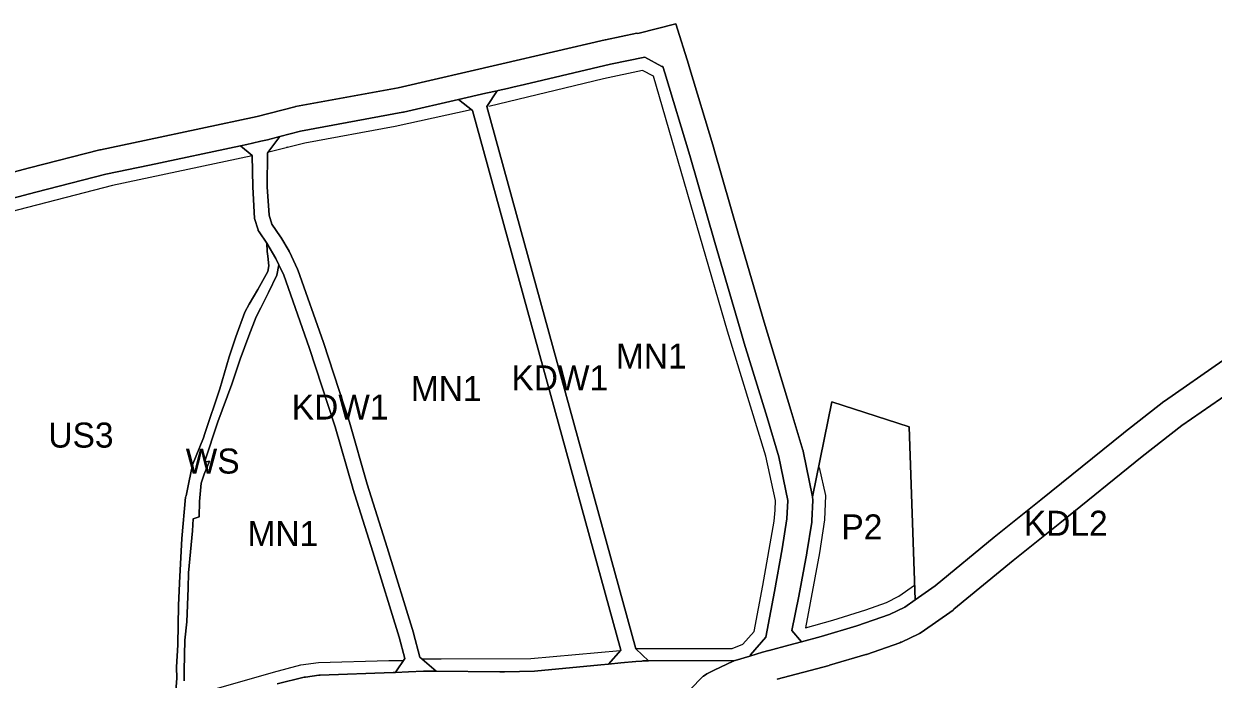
# Model space of a CAD drawing. Extents: x -284239 to -281592, y 34477 to 37267.
# Drawn here: x -282543.7 to -282068.8, y 35402.1 to 35664 of the extents above; entities that cross this region are included whole.
import ezdxf

# ---------------------------------------------------------------- set-up
doc = ezdxf.new("R2010")
doc.units = 0
for name, color, linetype in [('linie_rozgraniczajace', 7, 'Continuous'), ('linie_zabudowy_nieprzekraczalne', 7, 'Continuous'), ('oznaczenia_przeznaczen', 7, 'Continuous')]:
    doc.layers.add(name, color=color, linetype=linetype)

msp = doc.modelspace()

# ---------------------------------------------------------------- linework, layer by layer
at = {"layer": 'linie_rozgraniczajace'}
for points in [[(-282156.216, 35458.855), (-282156.283, 35458.799), (-282179.747, 35439.408), (-282187.748, 35433.765), (-282190.221, 35502.982), (-282221.032, 35512.932), (-282228.711, 35474.935), (-282232.469, 35493.155), (-282232.556, 35493.436), (-282232.577, 35493.581), (-282237.363, 35509.534), (-282248.119, 35544.76), (-282258.185, 35579.393), (-282268.146, 35614.173), (-282268.164, 35614.23), (-282278.129, 35647.32), (-282278.149, 35647.379), (-282283.402, 35663.97), (-282298.561, 35660.058), (-282298.939, 35660.172), (-282311.469, 35657.61), (-282311.549, 35657.586), (-282311.618, 35657.578), (-282352.828, 35647.901), (-282394.218, 35638.42), (-282435.165, 35630.866), (-282435.363, 35630.808), (-282435.518, 35630.788), (-282450.498, 35626.888), (-282495.528, 35617.291), (-282513.053, 35613.649), (-282513.187, 35613.608), (-282513.283, 35613.596), (-282541.365, 35606.362), (-282593.067, 35592.733)], [(-282513.283, 35613.596), (-282513.187, 35613.608), (-282513.053, 35613.649), (-282495.528, 35617.291), (-282450.498, 35626.888), (-282435.518, 35630.788), (-282435.363, 35630.808), (-282435.165, 35630.866), (-282394.218, 35638.42), (-282352.828, 35647.901), (-282311.618, 35657.578), (-282311.549, 35657.586), (-282311.469, 35657.61), (-282298.939, 35660.172), (-282298.561, 35660.058), (-282283.402, 35663.97), (-282278.149, 35647.379), (-282278.129, 35647.32), (-282268.164, 35614.23), (-282268.146, 35614.173), (-282258.185, 35579.393), (-282248.119, 35544.76), (-282237.363, 35509.534), (-282232.577, 35493.581), (-282232.556, 35493.436), (-282232.469, 35493.155), (-282228.711, 35474.935), (-282228.614, 35473.683), (-282229.013, 35465.427), (-282229.033, 35465.338), (-282229.068, 35464.891), (-282231.004, 35452.593), (-282231.018, 35452.542), (-282231.024, 35452.471), (-282234.16, 35435.315), (-282237.037, 35421.583), (-282233.186, 35417.056), (-282238.271, 35415.694), (-282246.036, 35413.615), (-282246.144, 35413.578), (-282246.19, 35413.572), (-282248.711, 35412.824), (-282253.777, 35411.321), (-282253.537, 35411.853), (-282247.441, 35418.875), (-282243.99, 35437.145), (-282240.873, 35454.208), (-282238.988, 35466.179), (-282238.633, 35473.534), (-282242.219, 35490.919), (-282246.935, 35506.639), (-282255.995, 35536.311), (-282257.694, 35541.88), (-282257.712, 35541.937), (-282267.792, 35576.62), (-282277.75, 35611.387), (-282287.694, 35644.402), (-282288.475, 35646.868), (-282288.904, 35646.911), (-282295.714, 35650.637), (-282309.406, 35647.825), (-282343.721, 35639.768), (-282348.468, 35638.653), (-282350.571, 35638.16), (-282354.321, 35637.3), (-282354.712, 35637.211), (-282359.156, 35636.193), (-282370.167, 35633.67), (-282392.089, 35628.648), (-282392.192, 35628.637), (-282392.299, 35628.605), (-282433.173, 35621.065), (-282441.511, 35618.894), (-282446.32, 35617.642), (-282449.038, 35617.034), (-282452.307, 35616.302), (-282454.677, 35615.772), (-282457.172, 35615.24), (-282493.469, 35607.506), (-282510.903, 35603.883), (-282538.845, 35596.685), (-282590.976, 35582.942)], [(-282590.976, 35582.942), (-282538.845, 35596.685), (-282510.903, 35603.883), (-282493.469, 35607.506), (-282457.172, 35615.24), (-282452.487, 35611.337), (-282452.198, 35598.751), (-282451.624, 35586.227), (-282450.145, 35581.613), (-282450.094, 35581.53), (-282450.07, 35581.414), (-282449.769, 35580.86), (-282446.604, 35576.266), (-282446.453, 35573.013), (-282446.243, 35571.086), (-282445.833, 35567.312), (-282446.243, 35564.933), (-282450.304, 35557.755), (-282453.75, 35551.93), (-282455.472, 35548.73), (-282459, 35538.885), (-282461.666, 35530.887), (-282465.44, 35518.17), (-282471.429, 35500.286), (-282471.936, 35498.59), (-282476.263, 35487.718), (-282477.805, 35480.653), (-282478.889, 35475.341), (-282479.059, 35474.771), (-282480.577, 35458.323), (-282481.561, 35440.602), (-282481.519, 35440.508), (-282481.922, 35431.499), (-282482.206, 35415.976), (-282482.217, 35415.826), (-282482.71, 35406.884), (-282482.521, 35402.543), (-282482.916, 35397.302)], [(-282593.067, 35592.733), (-282541.365, 35606.362), (-282513.283, 35613.596)], [(-282482.916, 35397.302), (-282482.521, 35402.543), (-282482.71, 35406.884), (-282482.217, 35415.826), (-282482.206, 35415.976), (-282481.922, 35431.499), (-282481.519, 35440.508), (-282481.561, 35440.602), (-282480.577, 35458.323), (-282479.059, 35474.771), (-282478.889, 35475.341), (-282477.805, 35480.653), (-282476.263, 35487.718), (-282471.936, 35498.59), (-282471.429, 35500.286), (-282465.44, 35518.17), (-282461.666, 35530.887), (-282459, 35538.885), (-282455.472, 35548.73), (-282453.75, 35551.93), (-282450.304, 35557.755), (-282446.243, 35564.933), (-282445.833, 35567.312), (-282446.243, 35571.086), (-282446.453, 35573.013), (-282446.604, 35576.266), (-282443.038, 35570.191), (-282441.853, 35567.671), (-282442.633, 35563.456), (-282445.997, 35556.647), (-282449.032, 35550.494), (-282450.919, 35546.885), (-282453.873, 35539.337), (-282457.277, 35529.943), (-282460.641, 35520.016), (-282466.261, 35504.88), (-282471.47, 35488.759), (-282469.583, 35489.252), (-282471.634, 35484.001), (-282472.906, 35480.35), (-282473.48, 35473.131), (-282473.726, 35466.896), (-282476.023, 35466.157), (-282476.352, 35461.317), (-282477.869, 35444.622), (-282478.033, 35438.469), (-282478.649, 35425.055), (-282479.387, 35417.672), (-282479.674, 35405.571), (-282479.674, 35401.469)], [(-282479.674, 35401.469), (-282479.674, 35405.571), (-282479.387, 35417.672), (-282478.649, 35425.055), (-282478.033, 35438.469), (-282477.869, 35444.622), (-282476.352, 35461.317), (-282476.023, 35466.157), (-282473.726, 35466.896), (-282473.48, 35473.131), (-282472.906, 35480.35), (-282471.634, 35484.001), (-282469.583, 35489.252), (-282471.47, 35488.759), (-282466.261, 35504.88), (-282460.641, 35520.016), (-282457.277, 35529.943), (-282453.873, 35539.337), (-282450.919, 35546.885), (-282449.032, 35550.494), (-282445.997, 35556.647), (-282442.633, 35563.456), (-282441.853, 35567.671), (-282439.871, 35563.456), (-282429.725, 35534.679), (-282419.309, 35502.955), (-282412.343, 35478.363), (-282412.317, 35478.283), (-282404.262, 35452.919), (-282393.836, 35418.903), (-282391.544, 35410.318), (-282395.099, 35405.02), (-282395.258, 35404.781), (-282396.138, 35404.729), (-282425.387, 35403.717), (-282425.443, 35403.705), (-282425.875, 35403.676), (-282431.247, 35402.959), (-282431.488, 35402.895), (-282431.773, 35402.86), (-282442.517, 35400.234)], [(-282277.68, 35397.974), (-282272.586, 35403.12), (-282272.27, 35403.328), (-282270.986, 35404.236), (-282268.024, 35405.653), (-282260.51, 35409.247), (-282260.362, 35409.28), (-282260.217, 35409.377), (-282259.804, 35409.523), (-282259.627, 35409.586), (-282253.777, 35411.321), (-282248.711, 35412.824), (-282246.19, 35413.572), (-282246.144, 35413.578), (-282246.036, 35413.615), (-282238.271, 35415.694), (-282233.186, 35417.056), (-282225.273, 35419.175), (-282211.077, 35423.383), (-282198.081, 35427.898), (-282191.894, 35430.84), (-282187.748, 35433.765), (-282179.747, 35439.408), (-282156.283, 35458.799), (-282156.216, 35458.855), (-282137.557, 35473.76), (-282104.605, 35500.451), (-282104.578, 35500.467), (-282104.517, 35500.521), (-282088.518, 35512.991), (-282088.41, 35513.053), (-282088.246, 35513.191), (-282064.901, 35529.361)], [(-282064.901, 35529.361), (-282088.246, 35513.191), (-282088.41, 35513.053), (-282088.518, 35512.991), (-282104.517, 35500.521), (-282104.578, 35500.467), (-282104.605, 35500.451), (-282137.557, 35473.76), (-282156.216, 35458.855)], [(-282242.854, 35402.044), (-282222.092, 35407.604), (-282221.984, 35407.64), (-282221.939, 35407.647), (-282207.534, 35411.917), (-282207.316, 35411.994), (-282207.27, 35412.002), (-282193.832, 35416.671), (-282193.553, 35416.846), (-282193.225, 35416.92), (-282186.279, 35420.222), (-282186.087, 35420.358), (-282185.397, 35420.738), (-282172.643, 35429.734), (-282172.397, 35429.942), (-282172.279, 35430.013), (-282148.688, 35449.51), (-282130.051, 35464.397), (-282130.024, 35464.42), (-282097.096, 35491.091), (-282081.274, 35503.422), (-282058.185, 35519.415)], [(-282058.185, 35519.415), (-282081.274, 35503.422), (-282097.096, 35491.091), (-282130.024, 35464.42), (-282130.051, 35464.397), (-282148.688, 35449.51), (-282172.279, 35430.013), (-282172.397, 35429.942), (-282172.643, 35429.734), (-282185.397, 35420.738), (-282186.087, 35420.358), (-282186.279, 35420.222), (-282193.225, 35416.92), (-282193.553, 35416.846), (-282193.832, 35416.671), (-282207.27, 35412.002), (-282207.316, 35411.994), (-282207.534, 35411.917), (-282221.939, 35407.647), (-282221.984, 35407.64), (-282222.092, 35407.604), (-282242.854, 35402.044)], [(-282442.517, 35400.234), (-282431.773, 35402.86), (-282431.488, 35402.895), (-282431.247, 35402.959), (-282425.875, 35403.676), (-282425.443, 35403.705), (-282425.387, 35403.717), (-282396.138, 35404.729), (-282395.258, 35404.781), (-282390.145, 35405.078), (-282384.024, 35405.317), (-282379.053, 35405.273), (-282353.58, 35405.049), (-282351.752, 35405.033), (-282339.773, 35405.236), (-282313.269, 35407.865), (-282313.233, 35407.868), (-282310.234, 35408.141), (-282305.256, 35408.594), (-282299.299, 35409.135), (-282296.907, 35409.353), (-282296.455, 35409.373), (-282296.414, 35409.37), (-282294.264, 35409.382), (-282259.804, 35409.523), (-282260.217, 35409.377), (-282260.362, 35409.28), (-282260.51, 35409.247), (-282268.024, 35405.653), (-282270.986, 35404.236), (-282272.27, 35403.328), (-282272.586, 35403.12), (-282277.68, 35397.974)]]:
    msp.add_lwpolyline(points, dxfattribs=at)
for points in [[(-282358.768, 35630.942), (-282354.712, 35637.211), (-282354.321, 35637.3), (-282350.571, 35638.16), (-282348.468, 35638.653), (-282343.721, 35639.768), (-282309.406, 35647.825), (-282295.714, 35650.637), (-282288.904, 35646.911), (-282288.475, 35646.868), (-282287.694, 35644.402), (-282277.75, 35611.387), (-282267.792, 35576.62), (-282257.712, 35541.937), (-282257.694, 35541.88), (-282255.995, 35536.311), (-282246.935, 35506.639), (-282242.219, 35490.919), (-282238.633, 35473.534), (-282238.988, 35466.179), (-282240.873, 35454.208), (-282243.99, 35437.145), (-282247.441, 35418.875), (-282253.537, 35411.853), (-282253.777, 35411.321), (-282259.627, 35409.586), (-282259.804, 35409.523), (-282294.264, 35409.382), (-282294.277, 35409.407), (-282299.299, 35414.238)], [(-282446.447, 35598.763), (-282446.398, 35612.464), (-282446.237, 35612.592), (-282441.511, 35618.894), (-282433.173, 35621.065), (-282392.299, 35628.605), (-282392.192, 35628.637), (-282392.089, 35628.648), (-282370.167, 35633.67), (-282364.509, 35629.296), (-282305.265, 35413.72), (-282310.234, 35408.141), (-282313.233, 35407.868), (-282313.269, 35407.865), (-282339.773, 35405.236), (-282351.752, 35405.033), (-282353.58, 35405.049), (-282379.053, 35405.273), (-282379.062, 35405.313), (-282385.518, 35410.945), (-282388.055, 35420.506), (-282388.08, 35420.581), (-282388.084, 35420.609), (-282398.534, 35454.705), (-282406.583, 35480.044), (-282413.585, 35504.742), (-282424.042, 35536.594), (-282424.056, 35536.644), (-282434.263, 35565.593), (-282434.343, 35565.721), (-282434.377, 35565.872), (-282437.66, 35572.855), (-282437.681, 35572.885), (-282437.774, 35573.073), (-282440.997, 35578.684), (-282441.059, 35578.765), (-282441.128, 35578.891), (-282444.587, 35583.914), (-282445.761, 35587.434)], [(-282370.167, 35633.67), (-282359.156, 35636.193), (-282354.712, 35637.211), (-282358.768, 35630.942), (-282299.299, 35414.238), (-282294.277, 35409.407), (-282294.264, 35409.382), (-282296.414, 35409.37), (-282296.455, 35409.373), (-282296.907, 35409.353), (-282299.299, 35409.135), (-282305.256, 35408.594), (-282310.234, 35408.141), (-282305.265, 35413.72), (-282364.509, 35629.296)], [(-282457.172, 35615.24), (-282454.677, 35615.772), (-282452.307, 35616.302), (-282449.038, 35617.034), (-282446.32, 35617.642), (-282441.511, 35618.894), (-282446.237, 35612.592), (-282446.398, 35612.464), (-282446.447, 35598.763), (-282445.761, 35587.434), (-282444.587, 35583.914), (-282441.128, 35578.891), (-282441.059, 35578.765), (-282440.997, 35578.684), (-282437.774, 35573.073), (-282437.681, 35572.885), (-282437.66, 35572.855), (-282434.377, 35565.872), (-282434.343, 35565.721), (-282434.263, 35565.593), (-282424.056, 35536.644), (-282424.042, 35536.594), (-282413.585, 35504.742), (-282406.583, 35480.044), (-282398.534, 35454.705), (-282388.084, 35420.609), (-282388.08, 35420.581), (-282388.055, 35420.506), (-282385.518, 35410.945), (-282379.062, 35405.313), (-282379.053, 35405.273), (-282384.024, 35405.317), (-282390.145, 35405.078), (-282395.258, 35404.781), (-282395.099, 35405.02), (-282391.544, 35410.318), (-282393.836, 35418.903), (-282404.262, 35452.919), (-282412.317, 35478.283), (-282412.343, 35478.363), (-282419.309, 35502.955), (-282429.725, 35534.679), (-282439.871, 35563.456), (-282441.853, 35567.671), (-282443.038, 35570.191), (-282446.604, 35576.266), (-282449.769, 35580.86), (-282450.07, 35581.414), (-282450.094, 35581.53), (-282450.145, 35581.613), (-282451.624, 35586.227), (-282452.198, 35598.751), (-282452.487, 35611.337)], [(-282237.037, 35421.583), (-282234.16, 35435.315), (-282231.024, 35452.471), (-282231.018, 35452.542), (-282231.004, 35452.593), (-282229.068, 35464.891), (-282229.033, 35465.338), (-282229.013, 35465.427), (-282228.614, 35473.683), (-282228.711, 35474.935), (-282221.032, 35512.932), (-282190.221, 35502.982), (-282187.748, 35433.765), (-282191.894, 35430.84), (-282198.081, 35427.898), (-282211.077, 35423.383), (-282225.273, 35419.175), (-282233.186, 35417.056)]]:
    msp.add_lwpolyline(points, close=True, dxfattribs=at)
at = {"layer": 'linie_zabudowy_nieprzekraczalne'}
for points in [[(-282299.436, 35414.298), (-282292.283, 35414.328), (-282260.798, 35414.328), (-282256.564, 35416.048), (-282252.066, 35421.208), (-282248.627, 35439.53), (-282244.129, 35465.195), (-282243.732, 35469.56), (-282243.6, 35473.529), (-282247.436, 35491.19), (-282262.65, 35541.13), (-282273.762, 35579.23), (-282292.283, 35643.061), (-282296.649, 35645.31), (-282312.259, 35642.003), (-282358.005, 35630.965)], [(-282364.995, 35629.605), (-282395.338, 35622.887), (-282431.454, 35616.272), (-282446.413, 35612.472)], [(-282438.517, 35614.702), (-282438.598, 35614.685)], [(-282452.498, 35611.149), (-282508.316, 35599.405), (-282545.754, 35589.681), (-282587.823, 35578.569), (-282589.543, 35575.262), (-282583.458, 35539.08), (-282574.462, 35485.303), (-282568.244, 35452.362), (-282560.571, 35414.064), (-282549.855, 35360.486), (-282546.019, 35354.4), (-282544.299, 35353.606), (-282539.669, 35354.268), (-282518.634, 35379.8), (-282507.39, 35389.457), (-282505.008, 35391.045), (-282499.055, 35393.426), (-282483.18, 35395.411)], [(-282226.137, 35486.692), (-282223.623, 35475.447), (-282224.02, 35465.79), (-282226.005, 35452.561), (-282231.561, 35422.663), (-282220.713, 35425.705), (-282207.484, 35429.807), (-282199.282, 35432.717), (-282194.255, 35435.231), (-282188.037, 35439.596)], [(-282384.632, 35410.197), (-282377.082, 35410.161), (-282341.231, 35410.293), (-282305.522, 35413.505)], [(-282479.741, 35395.808), (-282469.554, 35397.527), (-282444.022, 35404.936), (-282433.042, 35407.78), (-282426.03, 35408.706), (-282397.984, 35409.5), (-282392.041, 35409.536)]]:
    msp.add_lwpolyline(points, dxfattribs=at)

# ---------------------------------------------------------------- texts
at = {"layer": 'oznaczenia_przeznaczen'}
for s, p in [('MN1', (-282307.28, 35526.218)), ('KDW1', (-282348.981, 35517.483)), ('MN1', (-282389.145, 35513.205)), ('KDW1', (-282436.695, 35505.839)), ('US3', (-282533.881, 35494.624)), ('WS', (-282479.037, 35484.252)), ('P2', (-282217.225, 35457.93)), ('KDL2', (-282144.37, 35459.397)), ('MN1', (-282454.358, 35455.241))]:
    msp.add_text(s, height=10, dxfattribs=at).set_placement(p)

doc.saveas('drawing.dxf')
